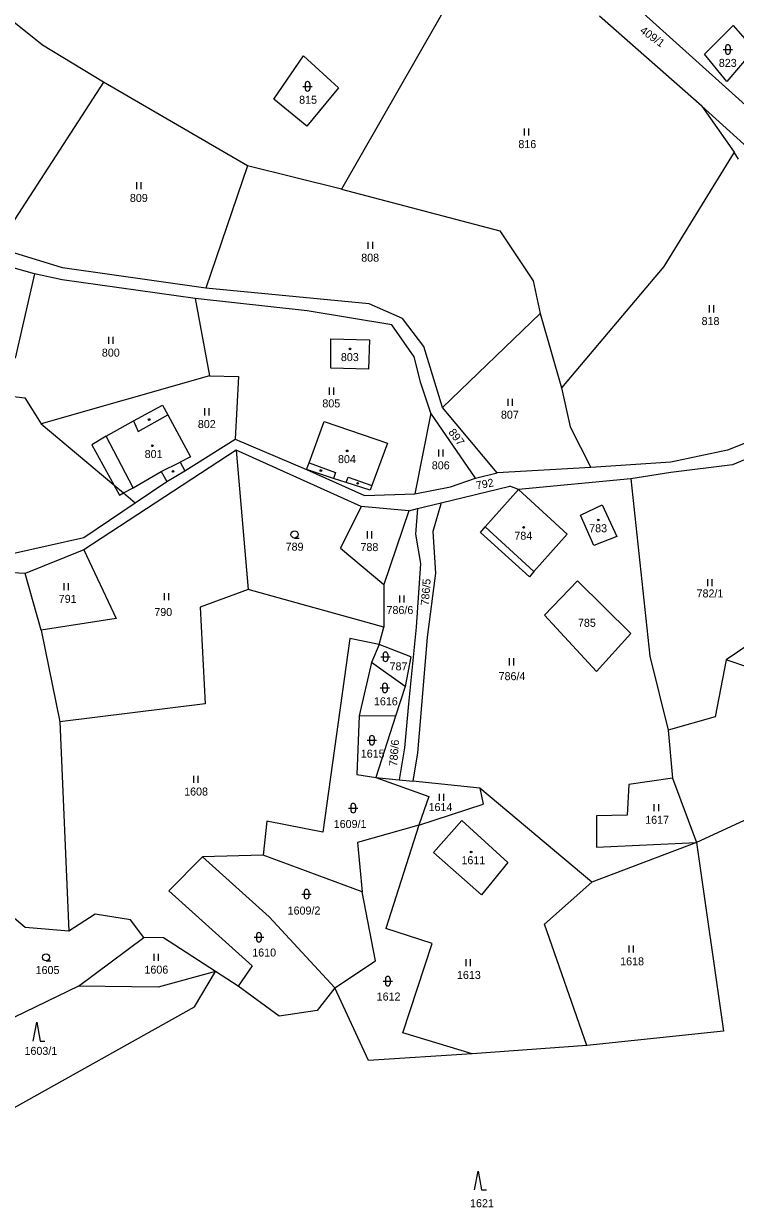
# Model space of a CAD drawing. Extents: x -670359 to -660124, y -978807 to -970072.
# Drawn here: x -669159.3 to -669008.2, y -978041.6 to -977790.2 of the extents above; entities that cross this region are included whole.
import ezdxf

# ---------------------------------------------------------------- set-up
doc = ezdxf.new("R2010")
doc.units = 0
for name, color, linetype in [('Hranice parcel', 7, 'Continuous'), ('Parcelní čísla', 7, 'Continuous'), ('Vnitřní kresba', 7, 'Continuous'), ('Značky budov', 7, 'Continuous'), ('Značky kultur', 7, 'Continuous')]:
    doc.layers.add(name, color=color, linetype=linetype)

msp = doc.modelspace()

# ---------------------------------------------------------------- linework, layer by layer
at = {"layer": 'Hranice parcel'}
msp.add_line((-668975.51, -977835.05), (-669029.85, -977786.03), dxfattribs=at)
for points in [[(-669155.29, -977794.72), (-669193.7, -977763.96)], [(-669067.56, -977782.96), (-669091.81, -977825.3)], [(-669015.27, -977807.68), (-669036.99, -977788.57)], [(-669014.75, -977796.63), (-669008.65, -977790.57)], [(-669008.65, -977790.57), (-669004.18, -977795.7)], [(-669142.34, -977802.6), (-669155.29, -977794.72)], [(-669106.16, -977806.22), (-669099.88, -977797.03)], [(-669099.88, -977797.03), (-669092.46, -977803.78)], [(-669009.97, -977802.49), (-669014.75, -977796.63)], [(-669004.18, -977795.7), (-669009.97, -977802.49)], [(-669142.34, -977802.6), (-669165.12, -977837.74)], [(-669111.73, -977820.37), (-669142.34, -977802.6)], [(-669092.46, -977803.78), (-669099.13, -977811.92)], [(-669099.13, -977811.92), (-669106.16, -977806.22)], [(-668995.95, -977825.18), (-669015.27, -977807.68)], [(-669015.27, -977807.68), (-669008.42, -977817.46)], [(-669008.42, -977817.46), (-669023.39, -977841.74)], [(-669007.54, -977818.98), (-669008.42, -977817.46)], [(-669111.73, -977820.37), (-669120.62, -977846.35)], [(-669091.81, -977825.3), (-669111.73, -977820.37)], [(-669091.81, -977825.3), (-669058.2, -977834.2)], [(-669058.2, -977834.2), (-669051.11, -977844.79)], [(-669151.04, -977842.02), (-669165.12, -977837.74)], [(-669156.97, -977843.29), (-669162.01, -977841.91)], [(-669120.62, -977846.35), (-669151.04, -977842.02)], [(-669023.39, -977841.74), (-669045.1, -977867.53)], [(-669156.97, -977843.29), (-669161.03, -977861.2)], [(-669151.05, -977844.58), (-669156.97, -977843.29)], [(-669122.87, -977848.58), (-669151.05, -977844.58)], [(-669051.11, -977844.79), (-669049.61, -977851.75)], [(-669085.88, -977849.65), (-669120.62, -977846.35)], [(-669099.1, -977851.13), (-669122.87, -977848.58)], [(-669122.87, -977848.58), (-669119.81, -977865)], [(-669078.84, -977852.79), (-669085.88, -977849.65)], [(-669081.09, -977854.14), (-669099.1, -977851.13)], [(-669074.3, -977858.72), (-669078.84, -977852.79)], [(-669049.61, -977851.75), (-669070.34, -977871.7)], [(-669049.61, -977851.75), (-669045.1, -977867.53)], [(-669076.39, -977860.96), (-669081.09, -977854.14)], [(-669094.05, -977863.37), (-669094.03, -977857.13)], [(-669094.03, -977857.13), (-669085.86, -977857.32)], [(-669085.86, -977857.32), (-669086.05, -977863.56)], [(-669070.34, -977871.7), (-669074.3, -977858.72)], [(-669074.97, -977866.56), (-669076.39, -977860.96)], [(-669119.81, -977865), (-669155.55, -977875.14)], [(-669119.81, -977865), (-669113.64, -977865.09)], [(-669113.64, -977865.09), (-669114.35, -977878.4)], [(-669086.05, -977863.56), (-669094.05, -977863.37)], [(-669072.82, -977872.89), (-669074.97, -977866.56)], [(-669045.1, -977867.53), (-669043.28, -977875.78)], [(-669166.34, -977868.79), (-669158.98, -977869.61)], [(-669158.98, -977869.61), (-669155.55, -977875.14)], [(-669135.96, -977874.54), (-669129.79, -977871.19)], [(-669129.79, -977871.19), (-669128.67, -977873.28)], [(-669072.82, -977872.89), (-669076.24, -977890.01)], [(-669063.34, -977886.68), (-669072.82, -977872.89)], [(-669058.77, -977885.58), (-669070.34, -977871.7)], [(-669155.55, -977875.14), (-669140.09, -977888.13)], [(-669141.74, -977877.8), (-669135.96, -977874.54)], [(-669128.67, -977873.28), (-669123.82, -977882.17)], [(-669098.68, -977883.44), (-669095.45, -977874.65)], [(-669095.45, -977874.65), (-669082.01, -977879.25)], [(-668992.35, -977873.84), (-669009.83, -977880.75)], [(-669136.01, -977888.78), (-669141.74, -977877.8)], [(-669043.28, -977875.78), (-669038.83, -977884.43)], [(-668993.16, -977877.36), (-669008.8, -977883.88)], [(-669125.03, -977885.13), (-669114.35, -977878.4)], [(-669114.35, -977878.4), (-669099.21, -977884.87)], [(-669082.01, -977879.25), (-669085.33, -977888.28)], [(-669114.17, -977880.78), (-669146.51, -977901.89)], [(-669123.82, -977882.17), (-669126.06, -977883.29)], [(-669087.62, -977892.7), (-669114.17, -977880.78)], [(-669114.17, -977880.78), (-669111.58, -977910.36)], [(-669009.83, -977880.75), (-669021.85, -977883.28)], [(-669128.88, -977887.44), (-669125.03, -977885.13)], [(-669126.06, -977883.29), (-669125.03, -977885.13)], [(-669099.21, -977884.87), (-669098.68, -977883.44)], [(-669099.21, -977884.87), (-669086.9, -977890.38)], [(-669093.49, -977886.74), (-669099.21, -977884.87)], [(-669063.34, -977886.68), (-669058.77, -977885.58)], [(-669038.83, -977884.43), (-669058.77, -977885.58)], [(-669021.85, -977883.28), (-669038.83, -977884.43)], [(-669021.85, -977885.52), (-669030.35, -977886.86)], [(-669008.8, -977883.88), (-669021.85, -977885.52)], [(-669135.59, -977891.92), (-669128.88, -977887.44)], [(-669090.77, -977887.62), (-669093.49, -977886.74)], [(-669085.7, -977889.28), (-669090.77, -977887.62)], [(-669068.63, -977888.51), (-669063.34, -977886.68)], [(-669030.35, -977886.86), (-669054.18, -977889.09)], [(-669030.35, -977886.86), (-669026.31, -977924.48)], [(-669140.09, -977888.13), (-669138.05, -977889.85)], [(-669138.05, -977889.85), (-669136.01, -977888.78)], [(-669138.05, -977889.85), (-669135.59, -977891.92)], [(-669086.9, -977890.38), (-669076.24, -977890.01)], [(-669085.33, -977888.28), (-669085.7, -977889.28)], [(-669076.24, -977890.01), (-669068.63, -977888.51)], [(-669070.61, -977891.95), (-669056.06, -977888.38)], [(-669061.26, -977897.07), (-669054.18, -977889.09)], [(-669054.18, -977889.09), (-669056.06, -977888.38)], [(-669054.18, -977889.09), (-669043.89, -977898.56)], [(-669146.51, -977899.33), (-669135.59, -977891.92)], [(-669087.62, -977892.7), (-669091.98, -977901.57)], [(-669077.46, -977893.61), (-669087.62, -977892.7)], [(-669075.66, -977893.16), (-669070.61, -977891.95)], [(-669070.61, -977891.95), (-669072.37, -977898)], [(-669041.07, -977894.56), (-669036.42, -977892.34)], [(-669036.42, -977892.34), (-669033.32, -977899.06)], [(-669077.46, -977893.61), (-669082.79, -977909.27)], [(-669077.46, -977893.61), (-669075.66, -977893.16)], [(-669075.66, -977893.16), (-669076.09, -977898.58)], [(-669038.21, -977900.97), (-669041.07, -977894.56)], [(-669072.37, -977898), (-669071.85, -977906.85)], [(-669062.3, -977898.26), (-669061.26, -977897.07)], [(-669161.65, -977902.73), (-669146.51, -977899.33)], [(-669076.09, -977898.58), (-669074.99, -977904.81)], [(-669051.85, -977907.65), (-669062.3, -977898.26)], [(-669043.89, -977898.56), (-669050.96, -977906.54)], [(-669033.32, -977899.06), (-669038.21, -977900.97)], [(-669146.51, -977901.89), (-669158.94, -977906.97)], [(-669146.51, -977901.89), (-669139.59, -977916.53)], [(-669091.98, -977901.57), (-669082.79, -977909.27)], [(-669158.94, -977906.97), (-669185.66, -977905.56)], [(-669074.99, -977904.81), (-669075.97, -977918.36)], [(-669155.54, -977919), (-669158.94, -977906.97)], [(-669071.85, -977906.85), (-669073.57, -977920.48)], [(-669050.96, -977906.54), (-669051.85, -977907.65)], [(-669111.58, -977910.36), (-669121.79, -977914.09)], [(-669082.77, -977918.35), (-669111.58, -977910.36)], [(-669082.79, -977909.27), (-669082.77, -977918.35)], [(-669048.7, -977915.77), (-669041.71, -977908.51)], [(-669041.71, -977908.51), (-669030.38, -977919.67)], [(-668989.35, -977911.21), (-669010.16, -977925.29)], [(-669121.79, -977914.09), (-669120.73, -977934.65)], [(-669139.59, -977916.53), (-669155.54, -977919)], [(-669037.69, -977927.73), (-669048.7, -977915.77)], [(-669155.54, -977919), (-669151.58, -977938.48)], [(-669090, -977920.75), (-669095.72, -977961.88)], [(-669083.77, -977922.01), (-669090, -977920.75)], [(-669083.77, -977922.01), (-669082.77, -977918.35)], [(-669075.97, -977918.36), (-669077.6, -977934.6)], [(-669073.57, -977920.48), (-669074.96, -977936.66)], [(-669030.38, -977919.67), (-669037.69, -977927.73)], [(-669083.77, -977922.01), (-669085.41, -977925.84)], [(-669077.07, -977924.65), (-669083.77, -977922.01)], [(-669077.07, -977924.65), (-669078.26, -977930.95)], [(-669026.31, -977924.48), (-669022.41, -977940.19)], [(-669010.16, -977925.29), (-669012.45, -977937.42)], [(-668980.01, -977935.45), (-669010.16, -977925.29)], [(-669085.41, -977925.84), (-669088.01, -977937.17)], [(-669078.26, -977930.95), (-669085.41, -977925.84)], [(-669078.26, -977930.95), (-669080.33, -977937.25)], [(-669120.73, -977934.65), (-669151.58, -977938.48)], [(-669077.6, -977934.6), (-669078.41, -977943.99)], [(-669088.01, -977937.17), (-669088.54, -977949.64)], [(-669080.33, -977937.25), (-669088.01, -977937.17)], [(-669080.33, -977937.25), (-669084.47, -977950.24)], [(-669074.96, -977936.66), (-669075.68, -977945.01)], [(-669012.45, -977937.42), (-669022.41, -977940.19)], [(-669151.58, -977938.48), (-669149.65, -977982.89)], [(-669022.41, -977940.19), (-669021.55, -977950.44)], [(-669078.41, -977943.99), (-669079.54, -977950.76)], [(-669075.68, -977945.01), (-669076.64, -977951.06)], [(-669088.54, -977949.64), (-669084.47, -977950.24)], [(-669084.47, -977950.24), (-669073.22, -977954.28)], [(-669084.47, -977950.24), (-669079.54, -977950.76)], [(-669079.54, -977950.76), (-669076.64, -977951.06)], [(-669021.55, -977950.44), (-669030.77, -977951.78)], [(-669021.55, -977950.44), (-669016.41, -977964.09)], [(-668985.45, -977949.79), (-669016.41, -977964.09)], [(-669062.4, -977952.56), (-669076.64, -977951.06)], [(-669038.68, -977972.49), (-669062.4, -977952.56)], [(-669062.4, -977952.56), (-669061.72, -977955.93)], [(-669030.77, -977951.78), (-669031.16, -977958.26)], [(-669073.22, -977954.28), (-669075.37, -977960.42)], [(-669075.37, -977960.42), (-669061.72, -977955.93)], [(-669031.16, -977958.26), (-669037.65, -977958.43)], [(-669037.65, -977958.43), (-669037.64, -977965.06)], [(-669107.62, -977959.51), (-669108.42, -977966.78)], [(-669095.72, -977961.88), (-669107.62, -977959.51)], [(-669075.37, -977960.42), (-669088.38, -977964.04)], [(-669075.37, -977960.42), (-669082.41, -977982.34)], [(-669072.23, -977966.17), (-669066.23, -977959.4)], [(-669066.23, -977959.4), (-669056.48, -977968.3)], [(-669088.38, -977964.04), (-669087.37, -977974.53)], [(-669016.41, -977964.09), (-669038.68, -977972.49)], [(-669037.64, -977965.06), (-669016.41, -977964.09)], [(-669016.41, -977964.09), (-669010.67, -978004.15)], [(-669121.31, -977967.12), (-669128.43, -977974.32)], [(-669108.42, -977966.78), (-669121.31, -977967.12)], [(-669107.11, -977979.83), (-669121.31, -977967.12)], [(-669087.37, -977974.53), (-669108.42, -977966.78)], [(-669062.08, -977975.16), (-669072.23, -977966.17)], [(-669056.48, -977968.3), (-669062.08, -977975.16)], [(-669048.7, -977981.42), (-669038.68, -977972.49)], [(-669128.43, -977974.32), (-669110.75, -977990.27)], [(-669084.56, -977989.19), (-669087.37, -977974.53)], [(-669158.93, -977982.15), (-669163.53, -977978.26)], [(-669144.09, -977979.27), (-669149.65, -977982.89)], [(-669136.58, -977980.47), (-669144.09, -977979.27)], [(-669133.74, -977984.26), (-669136.58, -977980.47)], [(-669093.19, -977994.94), (-669107.11, -977979.83)], [(-669149.65, -977982.89), (-669158.93, -977982.15)], [(-669072.51, -977985.56), (-669082.41, -977982.34)], [(-669039.68, -978007.19), (-669048.7, -977981.42)], [(-669147.61, -977994.59), (-669133.74, -977984.26)], [(-669129.58, -977984.31), (-669133.74, -977984.26)], [(-669118.52, -977991.47), (-669129.58, -977984.31)], [(-669078.8, -978004.53), (-669072.51, -977985.56)], [(-669110.75, -977990.27), (-669113.75, -977994.56)], [(-669093.19, -977994.94), (-669084.56, -977989.19)], [(-669118.52, -977991.47), (-669130.73, -977994.77)], [(-669123.02, -977998.99), (-669118.52, -977991.47)], [(-669113.75, -977994.56), (-669118.52, -977991.47)], [(-669147.61, -977994.59), (-669179.56, -978010)], [(-669130.73, -977994.77), (-669147.61, -977994.59)], [(-669105.02, -978000.97), (-669113.75, -977994.56)], [(-669093.19, -977994.94), (-669096.92, -977999.78)], [(-669086.06, -978010.37), (-669093.19, -977994.94)], [(-669162.99, -978021.31), (-669123.02, -977998.99)], [(-669096.92, -977999.78), (-669105.02, -978000.97)], [(-669064.04, -978008.93), (-669078.8, -978004.53)], [(-669010.67, -978004.15), (-669039.68, -978007.19)], [(-669039.68, -978007.19), (-669064.04, -978008.93)], [(-669064.04, -978008.93), (-669086.06, -978010.37)]]:
    msp.add_lwpolyline(points, dxfattribs=at)
at = {"layer": 'Vnitřní kresba'}
for points in [[(-669135.96, -977874.54), (-669134.93, -977876.78)], [(-669134.93, -977876.78), (-669128.67, -977873.28)], [(-669141.74, -977877.8), (-669144.79, -977879.63)], [(-669144.79, -977879.63), (-669140.09, -977888.13)], [(-669136.01, -977888.78), (-669130.07, -977885.28)], [(-669130.07, -977885.28), (-669126.06, -977883.29)], [(-669130.07, -977885.28), (-669128.88, -977887.44)], [(-669098.68, -977883.44), (-669093.04, -977885.49)], [(-669093.04, -977885.49), (-669093.49, -977886.74)], [(-669090.77, -977887.62), (-669090.35, -977886.46)], [(-669090.35, -977886.46), (-669085.33, -977888.28)], [(-669140.09, -977888.13), (-669138.9, -977890.29)], [(-669138.9, -977890.29), (-669138.05, -977889.85)], [(-669061.26, -977897.07), (-669050.96, -977906.54)]]:
    msp.add_lwpolyline(points, dxfattribs=at)
at = {"layer": 'Značky budov'}
for centre in [(-669089.99, -977859.24), (-669131.96, -977879.83), (-669090.57, -977880.9), (-669037.28, -977895.58), (-669053.13, -977897.17), (-669064.28, -977966.08)]:
    msp.add_circle(centre, 0.175, dxfattribs=at)
at = {"layer": 'Značky kultur'}
for p, q in [((-669010.76, -977795.66), (-669008.76, -977795.66)), ((-669010.26, -977795.16), (-669010.26, -977796.16)), ((-669009.26, -977795.16), (-669009.26, -977796.16)), ((-669099.99, -977803.49), (-669097.99, -977803.49)), ((-669099.49, -977802.99), (-669099.49, -977803.99)), ((-669098.49, -977802.99), (-669098.49, -977803.99)), ((-669052.99, -977812.41), (-669052.99, -977813.91)), ((-669051.99, -977813.91), (-669051.99, -977812.41)), ((-669135.32, -977823.84), (-669135.32, -977825.34)), ((-669134.32, -977825.34), (-669134.32, -977823.84)), ((-669086.17, -977836.53), (-669086.17, -977838.03)), ((-669085.17, -977838.03), (-669085.17, -977836.53)), ((-669013.76, -977849.99), (-669013.76, -977851.49)), ((-669012.76, -977851.49), (-669012.76, -977849.99)), ((-669141.23, -977856.69), (-669141.23, -977858.19)), ((-669140.23, -977858.19), (-669140.23, -977856.69)), ((-669094.42, -977867.47), (-669094.42, -977868.97)), ((-669093.42, -977868.97), (-669093.42, -977867.47)), ((-669056.51, -977869.86), (-669056.51, -977871.36)), ((-669055.51, -977871.36), (-669055.51, -977869.86)), ((-669120.85, -977871.86), (-669120.85, -977873.36)), ((-669119.85, -977873.36), (-669119.85, -977871.86)), ((-669071.23, -977880.62), (-669071.23, -977882.12)), ((-669070.23, -977882.12), (-669070.23, -977880.62)), ((-669086.33, -977897.99), (-669086.33, -977899.49)), ((-669085.33, -977899.49), (-669085.33, -977897.99)), ((-669101.76, -977899.41), (-669100.76, -977899.41)), ((-669014.12, -977908.12), (-669014.12, -977909.62)), ((-669013.12, -977909.62), (-669013.12, -977908.12)), ((-669150.71, -977908.98), (-669150.71, -977910.48)), ((-669149.71, -977910.48), (-669149.71, -977908.98)), ((-669129.41, -977911.11), (-669129.41, -977912.61)), ((-669128.41, -977912.61), (-669128.41, -977911.11)), ((-669079.48, -977911.6), (-669079.48, -977913.1)), ((-669078.48, -977913.1), (-669078.48, -977911.6)), ((-669083.46, -977924.63), (-669081.46, -977924.63)), ((-669082.96, -977924.13), (-669082.96, -977925.13)), ((-669081.96, -977924.13), (-669081.96, -977925.13)), ((-669056.23, -977924.96), (-669056.23, -977926.46)), ((-669055.23, -977926.46), (-669055.23, -977924.96)), ((-669083.08, -977930.74), (-669083.08, -977931.74)), ((-669082.08, -977930.74), (-669082.08, -977931.74)), ((-669083.58, -977931.24), (-669081.58, -977931.24)), ((-669086.33, -977942.35), (-669084.33, -977942.35)), ((-669085.83, -977941.85), (-669085.83, -977942.85)), ((-669084.83, -977941.85), (-669084.83, -977942.85)), ((-669123.19, -977949.9), (-669123.19, -977951.4)), ((-669122.19, -977951.4), (-669122.19, -977949.9)), ((-669071.05, -977953.75), (-669071.05, -977955.25)), ((-669070.05, -977955.25), (-669070.05, -977953.75)), ((-669025.46, -977955.9), (-669025.46, -977957.4)), ((-669024.46, -977957.4), (-669024.46, -977955.9)), ((-669090.29, -977956.77), (-669088.29, -977956.77)), ((-669089.79, -977956.27), (-669089.79, -977957.27)), ((-669088.79, -977956.27), (-669088.79, -977957.27)), ((-669100.21, -977975.03), (-669098.21, -977975.03)), ((-669099.71, -977974.53), (-669099.71, -977975.53)), ((-669098.71, -977974.53), (-669098.71, -977975.53)), ((-669110.31, -977984.21), (-669108.31, -977984.21)), ((-669109.81, -977983.71), (-669109.81, -977984.71)), ((-669108.81, -977983.71), (-669108.81, -977984.71)), ((-669030.77, -977985.96), (-669030.77, -977987.46)), ((-669029.77, -977987.46), (-669029.77, -977985.96)), ((-669131.66, -977987.72), (-669131.66, -977989.22)), ((-669130.66, -977989.22), (-669130.66, -977987.72)), ((-669154.5, -977989.21), (-669153.5, -977989.21)), ((-669065.42, -977988.85), (-669065.42, -977990.35)), ((-669064.42, -977990.35), (-669064.42, -977988.85)), ((-669082.96, -977993.52), (-669080.96, -977993.52)), ((-669082.46, -977993.02), (-669082.46, -977994.02)), ((-669081.46, -977993.02), (-669081.46, -977994.02))]:
    msp.add_line(p, q, dxfattribs=at)
for points in [[(-669157.23, -978006.25), (-669156.48, -978002.25), (-669155.73, -978006.25), (-669154.73, -978006.25)], [(-669063.54, -978037.87), (-669062.79, -978033.87), (-669062.04, -978037.87), (-669061.04, -978037.87)]]:
    msp.add_lwpolyline(points, dxfattribs=at)
for centre, radius in [((-669089.99, -977859.24), 0.175), ((-669132.63, -977874.25), 0.175), ((-669131.96, -977879.83), 0.175), ((-669090.57, -977880.9), 0.175), ((-669127.56, -977885.27), 0.175), ((-669096.16, -977885.08), 0.175), ((-669088.37, -977887.8), 0.175), ((-669037.28, -977895.58), 0.175), ((-669101.76, -977898.66), 0.75), ((-669053.13, -977897.17), 0.175), ((-669064.28, -977966.08), 0.175), ((-669154.5, -977988.46), 0.75)]:
    msp.add_circle(centre, radius, dxfattribs=at)
for centre, start, end in [((-669009.76, -977795.16), 0, 180), ((-669009.76, -977796.16), 180, 0), ((-669098.99, -977802.99), 0, 180), ((-669098.99, -977803.99), 180, 0), ((-669082.46, -977924.13), 0, 180), ((-669082.46, -977925.13), 180, 0), ((-669082.58, -977930.74), 0, 180), ((-669082.58, -977931.74), 180, 0), ((-669085.33, -977941.85), 0, 180), ((-669085.33, -977942.85), 180, 0), ((-669089.29, -977956.27), 0, 180), ((-669089.29, -977957.27), 180, 0), ((-669099.21, -977974.53), 0, 180), ((-669099.21, -977975.53), 180, 0), ((-669109.31, -977983.71), 0, 180), ((-669109.31, -977984.71), 180, 0), ((-669081.96, -977993.02), 0, 180), ((-669081.96, -977994.02), 180, 0)]:
    msp.add_arc(centre, 0.5, start, end, dxfattribs=at)

# ---------------------------------------------------------------- texts
at = {"layer": 'Parcelní čísla'}
for s, rotation, p in [('409/1', 324.3721, (-669028.59, -977791.97)), ('897', 307.2857, (-669069.19, -977876.98)), ('792', 10.7289, (-669063.07, -977889.12)), ('786/5', 85.5399, (-669073.28, -977913.79)), ('786/6', 85.3416, (-669080, -977947.96))]:
    msp.add_text(s, height=1.7, rotation=rotation, dxfattribs=at).set_placement(p)
for s, p in [('823', (-669011.69, -977799.36)), ('815', (-669100.78, -977807.19)), ('816', (-669054.24, -977816.61)), ('809', (-669136.71, -977828.04)), ('808', (-669087.6, -977840.73)), ('818', (-669015.35, -977854.19)), ('800', (-669142.66, -977860.89)), ('803', (-669091.92, -977861.84)), ('805', (-669095.85, -977871.67)), ('807', (-669057.94, -977874.06)), ('802', (-669122.28, -977876.06)), ('801', (-669133.57, -977882.43)), ('804', (-669092.53, -977883.5)), ('806', (-669072.62, -977884.82)), ('784', (-669055.09, -977899.77)), ('783', (-669039.21, -977898.18)), ('789', (-669103.65, -977902.11)), ('788', (-669087.76, -977902.19)), ('782/1', (-669016.41, -977912.03)), ('791', (-669151.82, -977913.18)), ('790', (-669131.52, -977915.98)), ('786/6', (-669082.23, -977915.56)), ('785', (-669041.59, -977918.27)), ('787', (-669081.58, -977927.52)), ('786/4', (-669058.44, -977929.6)), ('1616', (-669084.9, -977934.94)), ('1615', (-669087.69, -977946.05)), ('1608', (-669125.19, -977954.1)), ('1614', (-669073.31, -977957.4)), ('1617', (-669027.32, -977960.1)), ('1609/1', (-669093.44, -977960.99)), ('1611', (-669066.32, -977968.68)), ('1609/2', (-669103.22, -977979.38)), ('1610', (-669110.73, -977988.29)), ('1618', (-669032.63, -977990.16)), ('1605', (-669156.72, -977992.01)), ('1606', (-669133.62, -977991.92)), ('1613', (-669067.28, -977993.05)), ('1612', (-669084.32, -977997.64)), ('1603/1', (-669159.08, -978009.18)), ('1621', (-669064.5, -978041.53))]:
    msp.add_text(s, height=1.7, dxfattribs=at).set_placement(p)

doc.saveas('drawing.dxf')
